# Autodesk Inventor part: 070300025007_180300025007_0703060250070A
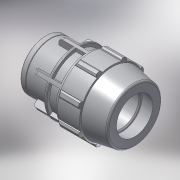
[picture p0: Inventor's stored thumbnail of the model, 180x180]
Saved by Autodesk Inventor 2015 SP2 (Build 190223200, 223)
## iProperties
Created: 2017-02
Part Number: 070300025007_180300025007_0703060250070A
Material: PVC-Piping
Description: PLASSON FEMALE ADAPTOR 25-3/4"
Document SubType Name: Modeling
Designer: KIM
Mass: 92.6774 g
Surface Area: 199.44 cm^2
Volume: 66.1981 cm^3
Density: 1.4 g/cm^3
Appearance: Smooth - White
Author: KIM
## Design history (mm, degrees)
derived "07030.ipt"
feature "Solid1::07030.ipt"
tag "TaggingFeature1"
body "Solid1"
other parameters: "d2" = 25, "d4" = 12.57143, "d5" = 22, "d7" = 54, "d9" = 12.57143, "d11" = 2.51429, "d12" = 43.2, "d13" = 120 deg, "d14" = 37.5, "d15" = 12 deg, "d16" = 48.6, "d18" = 1.25, "d19" = 35 deg, "d20" = 17.5 deg, "d21" = 50.22, "d23" = 0, "d25" = 360 deg, "d27" = 1.08, "d34" = 2.7, "d35" = 26.4, "d36" = 0, "d42" = 22, "d43" = 1.62, "d46" = 0.75, "d49" = 63, "d51" = 88, "d53" = 0.5, "d55" = 360 deg, "d61" = 21, "d63" = 24.117, "d64" = 29.33333, "d65" = 2.7, "d66" = 0.5, "d67" = 1, "d68" = 6.3, "d69" = 38.88, "d70" = 1.35, "d_" = 25, "E_" = 54, "H_" = 88, "l_" = 63, "l_2" = 21, "Rp_" = 24.117
